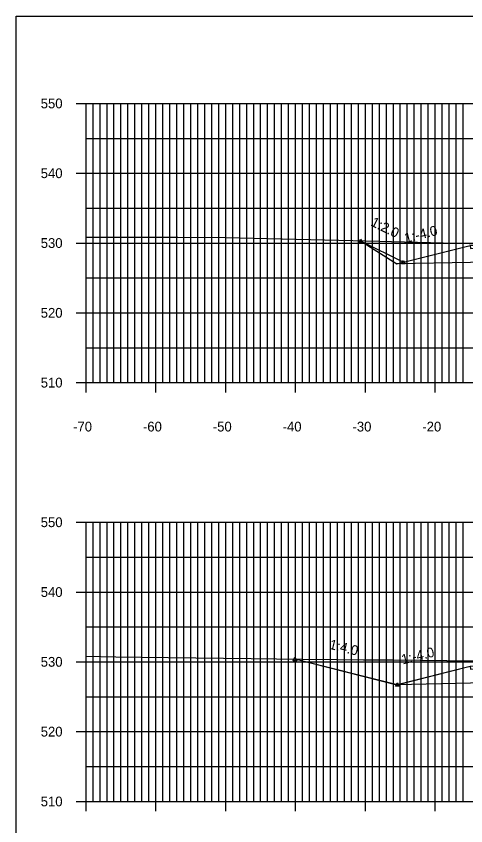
# Model space of a CAD drawing. Extents: x 1509063 to 1512863, y 401160 to 402918.
# Drawn here: x 1512182.7 to 1512247.1, y 402346.1 to 402462.1 of the extents above; entities that cross this region are included whole.
import ezdxf

# ---------------------------------------------------------------- set-up
doc = ezdxf.new("R2010")
doc.units = 0
for name, color, linetype in [('DD_P', 7, 'Continuous'), ('LCUT_P', 7, 'Continuous'), ('NBL1', 7, 'Continuous'), ('RBS_P', 7, 'Continuous'), ('XAX_P', 7, 'Continuous'), ('XAXTIC_P', 7, 'Continuous'), ('XAXTXT_P_T', 7, 'Continuous'), ('XGL_P', 7, 'Continuous'), ('XSL1_P', 7, 'Continuous'), ('XSL1_P_T', 7, 'Continuous'), ('XSLOG', 7, 'Continuous')]:
    doc.layers.add(name, color=color, linetype=linetype)

msp = doc.modelspace()

# ---------------------------------------------------------------- linework, layer by layer
at = {"layer": 'DD_P'}
for points in [[(1512232.04, 402429.89), (1512238.17, 402426.83), (1512247.73, 402429.22)], [(1512222.64, 402369.99), (1512237.29, 402366.33), (1512247.73, 402368.94)]]:
    msp.add_lwpolyline(points, dxfattribs=at)
for points in [[(1512238.17, 402427.08), (1512238.42, 402426.58), (1512237.92, 402426.58)], [(1512237.29, 402366.58), (1512237.54, 402366.08), (1512237.04, 402366.08)]]:
    msp.add_lwpolyline(points, close=True, dxfattribs=at)
at = {"layer": 'LCUT_P'}
for points in [[(1512232.04, 402430.14), (1512232.29, 402429.64), (1512231.79, 402429.64)], [(1512222.64, 402370.24), (1512222.89, 402369.74), (1512222.39, 402369.74)]]:
    msp.add_lwpolyline(points, close=True, dxfattribs=at)
at = {"layer": 'NBL1'}
msp.add_lwpolyline([(1512502.73, 402252.08), (1512182.73, 402252.08), (1512182.73, 402462.08), (1512502.73, 402462.08)], close=True, dxfattribs=at)
at = {"layer": 'RBS_P'}
for points in [[(1512247.8, 402428.8), (1512251.73, 402428.88), (1512262.72, 402429.1), (1512262.72, 402427.1), (1512251.73, 402426.88), (1512247.8, 402426.8), (1512237.22, 402426.59), (1512247.73, 402429.22), (1512247.73, 402429.22)], [(1512247.8, 402368.52), (1512251.73, 402368.6), (1512262.72, 402368.82), (1512262.72, 402366.82), (1512251.73, 402366.6), (1512247.8, 402366.52), (1512237.22, 402366.31), (1512247.73, 402368.94), (1512247.73, 402368.94)]]:
    msp.add_lwpolyline(points, close=True, dxfattribs=at)
at = {"layer": 'XAX_P'}
for p, q in [((1512192.73, 402409.58), (1512192.73, 402449.58)), ((1512192.73, 402409.58), (1512332.73, 402409.58)), ((1512192.73, 402349.58), (1512192.73, 402389.58)), ((1512192.73, 402349.58), (1512332.73, 402349.58))]:
    msp.add_line(p, q, dxfattribs=at)
at = {"layer": 'XAXTIC_P'}
for p, q in [((1512191.33, 402449.58), (1512194.13, 402449.58)), ((1512191.33, 402439.58), (1512194.13, 402439.58)), ((1512191.33, 402429.58), (1512194.13, 402429.58)), ((1512191.33, 402419.58), (1512194.13, 402419.58)), ((1512192.73, 402408.18), (1512192.73, 402410.98)), ((1512202.73, 402408.18), (1512202.73, 402410.98)), ((1512212.73, 402408.18), (1512212.73, 402410.98)), ((1512222.73, 402408.18), (1512222.73, 402410.98)), ((1512232.73, 402408.18), (1512232.73, 402410.98)), ((1512242.73, 402408.18), (1512242.73, 402410.98)), ((1512191.33, 402409.58), (1512194.13, 402409.58)), ((1512191.33, 402389.58), (1512194.13, 402389.58)), ((1512191.33, 402379.58), (1512194.13, 402379.58)), ((1512191.33, 402369.58), (1512194.13, 402369.58)), ((1512191.33, 402359.58), (1512194.13, 402359.58)), ((1512192.73, 402348.18), (1512192.73, 402350.98)), ((1512202.73, 402348.18), (1512202.73, 402350.98)), ((1512212.73, 402348.18), (1512212.73, 402350.98)), ((1512222.73, 402348.18), (1512222.73, 402350.98)), ((1512232.73, 402348.18), (1512232.73, 402350.98)), ((1512242.73, 402348.18), (1512242.73, 402350.98)), ((1512191.33, 402349.58), (1512194.13, 402349.58))]:
    msp.add_line(p, q, dxfattribs=at)
at = {"layer": 'XGL_P'}
for p, q in [((1512192.73, 402449.58), (1512332.73, 402449.58)), ((1512192.73, 402409.58), (1512192.73, 402449.58)), ((1512193.73, 402409.58), (1512193.73, 402449.58)), ((1512194.73, 402409.58), (1512194.73, 402449.58)), ((1512195.73, 402409.58), (1512195.73, 402449.58)), ((1512196.73, 402409.58), (1512196.73, 402449.58)), ((1512197.73, 402409.58), (1512197.73, 402449.58)), ((1512198.73, 402409.58), (1512198.73, 402449.58)), ((1512199.73, 402409.58), (1512199.73, 402449.58)), ((1512200.73, 402409.58), (1512200.73, 402449.58)), ((1512201.73, 402409.58), (1512201.73, 402449.58)), ((1512202.73, 402409.58), (1512202.73, 402449.58)), ((1512203.73, 402409.58), (1512203.73, 402449.58)), ((1512204.73, 402409.58), (1512204.73, 402449.58)), ((1512205.73, 402409.58), (1512205.73, 402449.58)), ((1512206.73, 402409.58), (1512206.73, 402449.58)), ((1512207.73, 402409.58), (1512207.73, 402449.58)), ((1512208.73, 402409.58), (1512208.73, 402449.58)), ((1512209.73, 402409.58), (1512209.73, 402449.58)), ((1512210.73, 402409.58), (1512210.73, 402449.58)), ((1512211.73, 402409.58), (1512211.73, 402449.58)), ((1512212.73, 402409.58), (1512212.73, 402449.58)), ((1512213.73, 402409.58), (1512213.73, 402449.58)), ((1512214.73, 402409.58), (1512214.73, 402449.58)), ((1512215.73, 402409.58), (1512215.73, 402449.58)), ((1512216.73, 402409.58), (1512216.73, 402449.58)), ((1512217.73, 402409.58), (1512217.73, 402449.58)), ((1512218.73, 402409.58), (1512218.73, 402449.58)), ((1512219.73, 402409.58), (1512219.73, 402449.58)), ((1512220.73, 402409.58), (1512220.73, 402449.58)), ((1512221.73, 402409.58), (1512221.73, 402449.58)), ((1512222.73, 402409.58), (1512222.73, 402449.58)), ((1512223.73, 402409.58), (1512223.73, 402449.58)), ((1512224.73, 402409.58), (1512224.73, 402449.58)), ((1512225.73, 402409.58), (1512225.73, 402449.58)), ((1512226.73, 402409.58), (1512226.73, 402449.58)), ((1512227.73, 402409.58), (1512227.73, 402449.58)), ((1512228.73, 402409.58), (1512228.73, 402449.58)), ((1512229.73, 402409.58), (1512229.73, 402449.58)), ((1512230.73, 402409.58), (1512230.73, 402449.58)), ((1512231.73, 402409.58), (1512231.73, 402449.58)), ((1512232.73, 402409.58), (1512232.73, 402449.58)), ((1512233.73, 402409.58), (1512233.73, 402449.58)), ((1512234.73, 402409.58), (1512234.73, 402449.58)), ((1512235.73, 402409.58), (1512235.73, 402449.58)), ((1512236.73, 402409.58), (1512236.73, 402449.58)), ((1512237.73, 402409.58), (1512237.73, 402449.58)), ((1512238.73, 402409.58), (1512238.73, 402449.58)), ((1512239.73, 402409.58), (1512239.73, 402449.58)), ((1512240.73, 402409.58), (1512240.73, 402449.58)), ((1512241.73, 402409.58), (1512241.73, 402449.58)), ((1512242.73, 402409.58), (1512242.73, 402449.58)), ((1512243.73, 402409.58), (1512243.73, 402449.58)), ((1512244.73, 402409.58), (1512244.73, 402449.58)), ((1512245.73, 402409.58), (1512245.73, 402449.58)), ((1512246.73, 402409.58), (1512246.73, 402449.58)), ((1512192.73, 402444.58), (1512332.73, 402444.58)), ((1512192.73, 402439.58), (1512332.73, 402439.58)), ((1512192.73, 402434.58), (1512332.73, 402434.58)), ((1512192.73, 402429.58), (1512332.73, 402429.58)), ((1512192.73, 402424.58), (1512332.73, 402424.58)), ((1512192.73, 402419.58), (1512332.73, 402419.58)), ((1512192.73, 402414.58), (1512332.73, 402414.58)), ((1512192.73, 402409.58), (1512332.73, 402409.58)), ((1512192.73, 402389.58), (1512332.73, 402389.58)), ((1512192.73, 402349.58), (1512192.73, 402389.58)), ((1512193.73, 402349.58), (1512193.73, 402389.58)), ((1512194.73, 402349.58), (1512194.73, 402389.58)), ((1512195.73, 402349.58), (1512195.73, 402389.58)), ((1512196.73, 402349.58), (1512196.73, 402389.58)), ((1512197.73, 402349.58), (1512197.73, 402389.58)), ((1512198.73, 402349.58), (1512198.73, 402389.58)), ((1512199.73, 402349.58), (1512199.73, 402389.58)), ((1512200.73, 402349.58), (1512200.73, 402389.58)), ((1512201.73, 402349.58), (1512201.73, 402389.58)), ((1512202.73, 402349.58), (1512202.73, 402389.58)), ((1512203.73, 402349.58), (1512203.73, 402389.58)), ((1512204.73, 402349.58), (1512204.73, 402389.58)), ((1512205.73, 402349.58), (1512205.73, 402389.58)), ((1512206.73, 402349.58), (1512206.73, 402389.58)), ((1512207.73, 402349.58), (1512207.73, 402389.58)), ((1512208.73, 402349.58), (1512208.73, 402389.58)), ((1512209.73, 402349.58), (1512209.73, 402389.58)), ((1512210.73, 402349.58), (1512210.73, 402389.58)), ((1512211.73, 402349.58), (1512211.73, 402389.58)), ((1512212.73, 402349.58), (1512212.73, 402389.58)), ((1512213.73, 402349.58), (1512213.73, 402389.58)), ((1512214.73, 402349.58), (1512214.73, 402389.58)), ((1512215.73, 402349.58), (1512215.73, 402389.58)), ((1512216.73, 402349.58), (1512216.73, 402389.58)), ((1512217.73, 402349.58), (1512217.73, 402389.58)), ((1512218.73, 402349.58), (1512218.73, 402389.58)), ((1512219.73, 402349.58), (1512219.73, 402389.58)), ((1512220.73, 402349.58), (1512220.73, 402389.58)), ((1512221.73, 402349.58), (1512221.73, 402389.58)), ((1512222.73, 402349.58), (1512222.73, 402389.58)), ((1512223.73, 402349.58), (1512223.73, 402389.58)), ((1512224.73, 402349.58), (1512224.73, 402389.58)), ((1512225.73, 402349.58), (1512225.73, 402389.58)), ((1512226.73, 402349.58), (1512226.73, 402389.58)), ((1512227.73, 402349.58), (1512227.73, 402389.58)), ((1512228.73, 402349.58), (1512228.73, 402389.58)), ((1512229.73, 402349.58), (1512229.73, 402389.58)), ((1512230.73, 402349.58), (1512230.73, 402389.58)), ((1512231.73, 402349.58), (1512231.73, 402389.58)), ((1512232.73, 402349.58), (1512232.73, 402389.58)), ((1512233.73, 402349.58), (1512233.73, 402389.58)), ((1512234.73, 402349.58), (1512234.73, 402389.58)), ((1512235.73, 402349.58), (1512235.73, 402389.58)), ((1512236.73, 402349.58), (1512236.73, 402389.58)), ((1512237.73, 402349.58), (1512237.73, 402389.58)), ((1512238.73, 402349.58), (1512238.73, 402389.58)), ((1512239.73, 402349.58), (1512239.73, 402389.58)), ((1512240.73, 402349.58), (1512240.73, 402389.58)), ((1512241.73, 402349.58), (1512241.73, 402389.58)), ((1512242.73, 402349.58), (1512242.73, 402389.58)), ((1512243.73, 402349.58), (1512243.73, 402389.58)), ((1512244.73, 402349.58), (1512244.73, 402389.58)), ((1512245.73, 402349.58), (1512245.73, 402389.58)), ((1512246.73, 402349.58), (1512246.73, 402389.58)), ((1512192.73, 402384.58), (1512332.73, 402384.58)), ((1512192.73, 402379.58), (1512332.73, 402379.58)), ((1512192.73, 402374.58), (1512332.73, 402374.58)), ((1512192.73, 402369.58), (1512332.73, 402369.58)), ((1512192.73, 402364.58), (1512332.73, 402364.58)), ((1512192.73, 402359.58), (1512332.73, 402359.58)), ((1512192.73, 402354.58), (1512332.73, 402354.58)), ((1512192.73, 402349.58), (1512332.73, 402349.58))]:
    msp.add_line(p, q, dxfattribs=at)
at = {"layer": 'XSL1_P'}
for points in [[(1512232.04, 402429.89), (1512237.22, 402426.59), (1512238.17, 402426.83), (1512247.73, 402429.22), (1512251.73, 402429.3), (1512262.73, 402429.52), (1512273.73, 402429.3), (1512277.73, 402429.22), (1512288.24, 402426.59), (1512289.69, 402426.23), (1512290.41, 402426.05), (1512295.35, 402429.06)], [(1512222.64, 402369.99), (1512237.22, 402366.31), (1512237.29, 402366.33), (1512247.73, 402368.94), (1512251.73, 402369.02), (1512262.73, 402369.24), (1512273.73, 402369.02), (1512277.73, 402368.94), (1512288.24, 402366.31), (1512290.41, 402365.77), (1512290.56, 402365.73), (1512295.19, 402368.04)]]:
    msp.add_lwpolyline(points, dxfattribs=at)
at = {"layer": 'XSLOG'}
for points in [[(1512192.73, 402430.44), (1512205.89, 402430.43), (1512212.69, 402430.38), (1512230.92, 402429.92), (1512247.59, 402429.52), (1512251.73, 402429.53), (1512255.03, 402429.52), (1512265.18, 402429.77), (1512267.56, 402429.84), (1512268.48, 402429.82), (1512277.14, 402429.69), (1512278.94, 402429.67), (1512279.14, 402429.66), (1512279.37, 402429.65), (1512299.91, 402428.89), (1512314.83, 402429.62), (1512317.82, 402429.91), (1512325.42, 402430.29), (1512331.09, 402432.29), (1512332.73, 402432.82)], [(1512192.73, 402370.4), (1512197, 402370.32), (1512204.5, 402370.19), (1512216.38, 402370.06), (1512223.63, 402369.98), (1512228.71, 402369.92), (1512232.47, 402369.88), (1512236.69, 402369.85), (1512248.26, 402369.74), (1512254.21, 402369.5), (1512254.76, 402369.49), (1512256.16, 402369.41), (1512260.7, 402369.12), (1512272.41, 402369.52), (1512273.05, 402369.55), (1512274.19, 402369.54), (1512284.8, 402369.47), (1512286.32, 402369.18), (1512288.55, 402368.76), (1512294.41, 402368.06), (1512301.75, 402367.81), (1512324.52, 402367.46), (1512332.73, 402369.01)]]:
    msp.add_lwpolyline(points, dxfattribs=at)

# ---------------------------------------------------------------- texts
at = {"layer": 'XAXTXT_P_T'}
for s, p in [('550', (1512186.24, 402448.88)), ('540', (1512186.24, 402438.88)), ('530', (1512186.24, 402428.88)), ('520', (1512186.24, 402418.88)), ('510', (1512186.24, 402408.88)), ('-70', (1512190.88, 402402.58)), ('-60', (1512200.88, 402402.58)), ('-50', (1512210.88, 402402.58)), ('-40', (1512220.88, 402402.58)), ('-30', (1512230.88, 402402.58)), ('-20', (1512240.88, 402402.58)), ('550', (1512186.24, 402388.88)), ('540', (1512186.24, 402378.88)), ('530', (1512186.24, 402368.88)), ('520', (1512186.24, 402358.88)), ('510', (1512186.24, 402348.88))]:
    msp.add_text(s, height=1.4, dxfattribs=at).set_placement(p)
at = {"layer": 'XSL1_P_T'}
for s, rotation, p in [('1:2.0', 333.4349, (1512233.38, 402432.13)), ('1:2.0', 333.4349, (1512233.38, 402432.13)), ('1:2.0', 333.4349, (1512233.38, 402432.13)), ('1:-4.0', 14.0362, (1512238.51, 402429.59)), ('1:-4.0', 14.0362, (1512238.51, 402429.59)), ('1:-4.0', 14.0362, (1512238.51, 402429.59)), ('1:4.0', 345.9638, (1512227.46, 402371.47)), ('1:4.0', 345.9638, (1512227.46, 402371.47)), ('1:4.0', 345.9638, (1512227.46, 402371.47)), ('1:-4.0', 14.0362, (1512238.07, 402369.2)), ('1:-4.0', 14.0362, (1512238.07, 402369.2)), ('1:-4.0', 14.0362, (1512238.07, 402369.2))]:
    msp.add_text(s, height=1.4, rotation=rotation, dxfattribs=at).set_placement(p)

doc.saveas('drawing.dxf')
